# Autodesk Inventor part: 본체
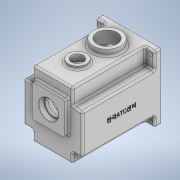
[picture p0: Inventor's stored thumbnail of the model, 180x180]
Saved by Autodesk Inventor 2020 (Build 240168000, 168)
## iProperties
Created: 2022-01
Part Number: 본체
Material: 일반
Document SubType Name: Modeling
Designer: user
Density: 1 g/cm^3
Appearance: 기본값
Author: user
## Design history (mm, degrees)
sketch "스케치1"
  geometry: L1 (-49, 55)-(49, 55); L2 (49, 55)-(49, -55); L3 (49, -55)-(-49, -55); L4 (-49, -55)-(-49, 55); L5 (-49, 55)-(49, -55); L6 (49, 55)-(-49, -55); 1 further point
  constraints: 12 end point, 2 midpoint, 2 parallel, 1 horizontal, 1 perpendicular
  dimensions: "d0" = 98 distance of L2.end L3.end; "d1" = 110 distance of L1.end L2.end
extrude "돌출1" new body sketch "스케치1" distance "d2" = 130; taper "d3" = 0 deg
sketch "스케치2"
  geometry: L1 (-27, 38)-(27, 38); L2 (27, 38)-(27, -16); L3 (27, -16)-(-27, -16); L4 (-27, -16)-(-27, 38); L5 (-27, 38)-(27, -16); L6 (27, 38)-(-27, -16); L7 (49, 55)-(-49, 55) reference; 4 further points
  constraints: 12 end point, 4 midpoint, 2 parallel, 1 horizontal, 1 perpendicular, 1 vertical alignment
  dimensions: "d48" = 11 distance of point (0, 0) point (0, 11); "d49" = 54 distance of L1.start L1.end; "d50" = 54 distance of L1.end L2.end
extrude "돌출2" join sketch "스케치2" distance "d6" = 7; taper "d7" = 0 deg
sketch "스케치3"
  geometry: L1 (0, -130)-(98, -130) reference; L2 (0, -130)-(16, -130); L3 (16, -130)-(16, -10); L4 (16, -10)-(0, -10); L5 (0, -10)-(0, -130); 2 further points
  constraints: 8 end point, 2 parallel, 1 horizontal, 1 perpendicular
  dimensions: "d8" = 16 distance of L4.end L3.end; "d9" = 120 distance of L3.end L2.end
extrude "돌출3" cut sketch "스케치3" distance "d10" = 27; taper "d11" = 0 deg
sketch "스케치4"
  geometry: L1 (-42, 48)-(42, 48); L2 (42, 48)-(42, -48); L3 (42, -48)-(-42, -48); L4 (-42, -48)-(-42, 48); L5 (-42, 48)-(42, -48); L6 (42, 48)-(-42, -48); 5 further points
  constraints: 12 end point, 4 coincident, 2 midpoint, 2 parallel, 1 horizontal, 1 perpendicular
  dimensions: "d12" = 84 distance of L2.end L3.end; "d13" = 96 distance of L1.end L2.end
hole "구멍1" sketch "스케치4" at (-42, 48), (42, 48), (42, -48), (-42, -48) diameter "d14" = 7; stored, may be unused: countersink angle "d18" = 90 deg, drill point angle "d20" = 0 deg; dims "d15" = 20, "d16" = 4, "d17" = 2, "d19" = 20
sketch "스케치5"
  geometry: C1 r 22.5 at (49, -40); C2 r 15 at (49, -89); 1 further point
  constraints: 2 centre point
  dimensions: "d22" = 45 diameter of C1; "d24" = 30 diameter of C2
extrude "돌출4" join sketch "스케치5" distance "d25" = 10; taper "d26" = 0 deg
sketch "스케치9"
  geometry: L1 (-23, 45)-(23, 45); L2 (23, 45)-(23, 16.676); L3 (23, 16.676)-(-23, 16.676); L4 (-23, 16.676)-(-23, 45); L5 (49, -55)-(-49, -55) reference; C1 r 42 at (0, -5); 5 further points
  constraints: 8 end point, 3 midpoint, 2 parallel, 2 vertical alignment, 1 centre point, 1 horizontal, 1 perpendicular
  dimensions: "d32" = 46 distance of L2.end L3.end; "d40" = 84 diameter of C1; "d41" = 50 distance from line of C1.centre L5; "d42" = 50 distance from line of L1 C1.centre
node "작업 평면1"
sketch "스케치11"
  geometry: 1 further point
sketch "스케치12"
  geometry: L1 (98, 10)-(98, 130) reference; L2 (82, 10)-(82, 130) reference; L3 (98, 130)-(82, 130); L4 (82, 130)-(82, 10); L5 (82, 10)-(98, 10); L6 (98, 10)-(98, 130); 3 further points
  constraints: 8 end point, 2 parallel, 1 horizontal, 1 perpendicular
  dimensions: "d36" = 16 distance of L5.end L2.start (derived); "d37" = 120 distance of L2.start L3.end (derived)
extrude "돌출7" cut sketch "스케치12" distance "d38" = 17; taper "d39" = 0 deg
extrude "돌출8" cut sketch "스케치9" distance "d43" = 121; taper "d44" = 0 deg
sketch "스케치14"
  geometry: L1 (23, 45)-(23, 30.143) reference; L2 (-23, 45)-(23, 45) reference; L3 (-23, 30.143)-(-23, 45) reference; L4 (-26, 31.729)-(-26, 48); L5 (-26, 48)-(26, 48); L6 (26, 48)-(26, 31.729); A1 r 42 centre (0, -5) between (-23, 30.143) and (23, 30.143) reference; A2 r 45 centre (0, -5) between (-26, 31.729) and (26, 31.729); 1 further point
  constraints: 6 end point, 2 point on circle, 1 centre point, 3 other
  dimensions: "d45" = 3 radial gap between concentric circles of A1 A2
extrude "돌출9" cut sketch "스케치14" distance "d46" = 9; taper "d47" = 0 deg
sketch "스케치15"
  geometry: L1 (27, 38)-(-27, 38) reference; C1 r 16 at (0, 11); 2 further points
  constraints: 1 centre point, 1 midpoint, 1 vertical alignment
  dimensions: "d51" = 32 diameter of C1; "d52" = 27 distance from line of C1.centre L1
extrude "돌출10" cut sketch "스케치15" distance "d53" = 8.3; taper "d54" = 0 deg
chamfer "모따기1" distance "d55" = 0.8; stored, may be unused: second distance "d56" = 2, angle "d57" = 30 deg
sketch "스케치16"
  geometry: 1 further point
sketch "스케치17"
  geometry: L1 (0, 0)-(0, 11); L2 (0, 0)-(0, -20); C1 r 21 at (0, 11); C2 r 15 at (0, -20); 2 further points
  constraints: 4 end point, 2 centre point, 2 coincident, 2 vertical
  dimensions: "d58" = 11 distance of L1.start L1.end; "d59" = 42 diameter of C1; "d60" = 20 distance of L1.start L2.end; "d61" = 30 diameter of C2
extrude "돌출11" join sketch "스케치17" distance "d62" = 7; taper "d63" = 0 deg
sketch "스케치18"
  geometry: L1 (0, 0)-(0, 11); C1 r 17.5 at (0, 11)
  constraints: 2 end point, 1 centre point, 1 coincident, 1 vertical
  dimensions: "d64" = 11 distance of L1.start L1.end; "d65" = 35 diameter of C1
extrude "돌출12" cut sketch "스케치18" distance "d66" = 10; taper "d67" = 0 deg
sketch "스케치19"
  geometry: L1 (27, 27)-(-27, 27) reference; C1 r 14 at (0, 0); 1 further point
  constraints: 1 centre point
  dimensions: "d68" = 28 diameter of C1; "d69" = 27 distance from line of C1.centre L1
extrude "돌출13" cut sketch "스케치19" stored distance "d70" = 10; taper "d71" = 0 deg
sketch "스케치20"
  geometry: L1 (0, 0)-(0, -20); C1 r 11 at (0, -20)
  constraints: 2 end point, 1 centre point, 1 coincident, 1 vertical
  dimensions: "d72" = 20 distance of L1.start L1.end; "d73" = 22 diameter of C1
extrude "돌출14" cut sketch "스케치20" distance "d74" = 7; taper "d75" = 0 deg
sketch "스케치21"
  geometry: C1 r 11 at (0, 0) reference; C2 r 9.5 at (0, 0); 1 further point
  constraints: 1 centre point, 1 coincident
  dimensions: "d76" = 19 diameter of C2
extrude "돌출15" cut sketch "스케치21" distance "d77" = 3; taper "d78" = 0 deg
sketch "스케치25"
  geometry: 1 further point
sketch "스케치26"
  geometry: 1 further point
sketch "스케치27"
  geometry: 1 further point
sketch "스케치28"
  geometry: C1 r 22.5 at (0, 0) reference; 2 further points
  constraints: 1 coincident
hole "구멍3" sketch "스케치28" at (0, 0) diameter "d87" = 33.376; stored, may be unused: countersink angle "d91" = 90 deg, drill point angle "d93" = 0 deg; dims "d88" = 77, "d89" = 4, "d90" = 2, "d92" = 77
sketch "스케치29"
  geometry: C1 r 15 at (49, -89); C2 r 16.688 at (49, -40) reference; 1 further point
  constraints: 1 centre point, 1 vertical alignment
  dimensions: "d94" = 30 diameter of C1; "d95" = 49 distance of C2.centre C1.centre
extrude "돌출16" join sketch "스케치29" distance "d96" = 5; taper "d97" = 0 deg
sketch "스케치30"
  geometry: C1 r 15 at (23, -32) reference; 1 further point
extrude "돌출17" cut sketch "스케치30" distance "d98" = 5; taper "d99" = 0 deg
sketch "스케치31"
  geometry: C1 r 15 at (0, 0) reference; C2 r 10 at (0, 0); 1 further point
  constraints: 1 centre point, 1 coincident
  dimensions: "d100" = 20 diameter of C2
extrude "돌출18" cut sketch "스케치31" stored distance "d101" = 5; taper "d102" = 0 deg
fillet "모깎기1" dims "d103" = 3
fillet "모깎기2" dims "d104" = 3
sketch "스케치32"
  geometry: 1 further point
sketch "스케치34"
  geometry: L1 (-23, 26.496)-(-23, 45) reference; L2 (23, 45)-(23, 26.496) reference; L3 (-23, 45)-(23, 45) reference; L4 (-36, -1)-(-41.809, -1); L5 (-36, -9)-(-41.809, -9); A1 r 18 centre (0, -20) between (-13.901, -8.565) and (13.901, -8.565) reference; A2 r 24 centre (0, 11) between (13.901, -8.565) and (-13.901, -8.565) reference; A3 r 39 centre (0, -5) between (-23, 26.496) and (23, 26.496) reference; A4 r 4 centre (-36, -5) between (-36, -1) and (-36, -9); A5 r 42 centre (0, -5) between (-23, 30.143) and (23, 30.143) reference; 1 further point
  constraints: 4 end point, 4 point on circle, 2 tangent, 1 centre point, 1 horizontal, 1 horizontal alignment, 1 parallel
  dimensions: "d105" = 36 distance of A4.centre A3.centre; "d106" = 8 diameter of A4
extrude "돌출19" join sketch "스케치34" stored distance "d107" = 5; taper "d108" = 0 deg
sketch "스케치35"
  geometry: A1 r 4 centre (-36, -5) between (-36, -9) and (-36, -1) reference; A2 r 4 centre (36, -5) between (36, -1) and (36, -9) reference; 3 further points
  constraints: 2 coincident
hole "구멍4" sketch "스케치35" at (-36, -5), (36, -5) diameter "d109" = 3.242; stored, may be unused: countersink angle "d113" = 90 deg, drill point angle "d115" = 118 deg; dims "d110" = 7, "d111" = 4, "d112" = 2, "d114" = 9
fillet "모깎기3" dims "d117" = 3
fillet "모깎기4" dims "d118" = 3
fillet "모깎기5" dims "d119" = 3
fillet "모깎기6" dims "d120" = 3
fillet "모깎기7" dims "d121" = 3
fillet "모깎기8" dims "d122" = 3
fillet "모깎기9" dims "d123" = 3
fillet "모깎기10" dims "d124" = 3
fillet "모깎기11" dims "d125" = 3
fillet "모깎기12" dims "d126" = 3
fillet "모깎기13" dims "d127" = 3
fillet "모깎기14" dims "d128" = 3
fillet "모깎기15" dims "d129" = 3
fillet "모깎기16" dims "d130" = 3
fillet "모깎기17" dims "d131" = 3
fillet "모깎기18" dims "d132" = 3
fillet "모깎기19" dims "d133" = 3
fillet "모깎기20" dims "d134" = 3
fillet "모깎기21" dims "d135" = 3
fillet "모깎기22" dims "d136" = 3
fillet "모깎기23" dims "d137" = 3
fillet "모깎기24" dims "d138" = 3
sketch "스케치37"
  geometry: L1 (-10.5, 124)-(-29.5, 124) reference; L2 (-10.5, 121)-(-10.5, 124) reference; L3 (-29.5, 121)-(-29.5, 124) reference; 1 further point
fillet "모깎기25" dims "d139" = 3
fillet "모깎기26" dims "d140" = 3
fillet "모깎기27" dims "d141" = 3
fillet "모깎기28" dims "d142" = 3
fillet "모깎기29" dims "d143" = 3
fillet "모깎기30" dims "d144" = 3
fillet "모깎기31" dims "d145" = 3
chamfer "모따기2" distance "d146" = 1; stored, may be unused: second distance "d147" = 2, angle "d148" = 30 deg
fillet "모깎기32" dims "d149" = 3
fillet "모깎기34" dims "d151" = 6
fillet "모깎기35" dims "d155" = 6
fillet "모깎기36" dims "d156" = 3
fillet "모깎기37" dims "d157" = 6
fillet "모깎기38" dims "d158" = 3
chamfer "모따기4" distance "d159" = 1; stored, may be unused: second distance "d160" = 2, angle "d161" = 30 deg
fillet "모깎기39" dims "d162" = 0.3
chamfer "모따기5" distance "d163" = 1; stored, may be unused: second distance "d164" = 2, angle "d165" = 30 deg
fillet "모깎기40" dims "d166" = 3
sketch "스케치38"
  geometry: L1 (-3, 87)-(-3, 70) reference; L2 (114, 63)-(0, 63) reference; 2 further points
  constraints: 1 other
  dimensions: "d167" = 65 distance from line of L1 point (62, 30); "d168" = 33 distance from line of L2 point (62, 30)
feature "엠보싱1" sketch "스케치38" dims "d169" = 0.5, "d170" = 0
node "솔리드1"
mirror "미러1"
mirror "미러3"
mirror "미러4"
node "투영된 루프1"
node "투영된 루프3"
feature "A9D066F2-1C7D-4E18-AEED-F7BC21143FA4" dims "d14" = 7, "d15" = 20, "d16" = 4, "d17" = 2, "d18" = 90 deg, "d19" = 20, "d20" = 0
